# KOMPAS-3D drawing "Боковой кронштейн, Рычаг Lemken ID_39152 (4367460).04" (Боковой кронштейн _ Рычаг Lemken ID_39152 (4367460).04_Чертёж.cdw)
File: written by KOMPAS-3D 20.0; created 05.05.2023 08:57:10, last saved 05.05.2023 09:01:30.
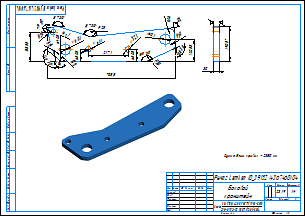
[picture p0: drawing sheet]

Sheet 1: A3, landscape

Document properties: Автор: factory; Полное имя файла: C:\Users\factory\Desktop\Чертежи\Рычаг Lemken ID_39152 (4367460)\Боковой кронштейн _ Рычаг Lemken ID_39152 (4367460).04_Чертёж.cdw; Масса: 23.1903

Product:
- Part/product: Боковой кронштейн  | designation Рычаг Lemken ID_39152 (4367460).04
    Материал: Лист$d32х1700х4200 ГОСТ 19903-2015;295-09Г2-ГС ГОСТ 19281-2014$ (density 7850 kg/m3)
    Масса: 23.1903

Title block, sheet 1: Наименование: Боковой / кронштейн; designation: Рычаг Lemken ID_39152 (4367460).04; Материал: Лист 30х1700х4200 ГОСТ 19903-2015 295-09Г2-ГС ГОСТ 19281-2014; Масса: 23,19; Количество листов документа: 1; Форматы листов документа: A3

Views: Вид 1, Спереди, Проекционный вид 2
Referenced files in C:\Users\factory\Desktop\Чертежи\Рычаг Lemken ID_39152 (4367460)\: Боковой кронштейн _ Рычаг Lemken ID_39152 (4367460).04_Рис.jpg, Боковой кронштейн _ Рычаг Lemken ID_39152 (4367460).04.m3d
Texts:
  Боковой кронштейн _ Рычаг Lemken ID_39152 (4367460).04_Рис.jpg
  Сумма длин кривых = 2350 мм
  Рычаг Lemken ID_39152 (4367460).04 Боковой кронштейн
Dimensions and other numbers on the sheet: 708,5; 60,1; 32,1; 146 30'; 140; 79 30'; 157 30'; 108 30'; 155 30'; 20; 25; 30; 217,1; 65,05; 64,05; 158,55; 120,55; 190,5; 1:4; 1; 23,19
